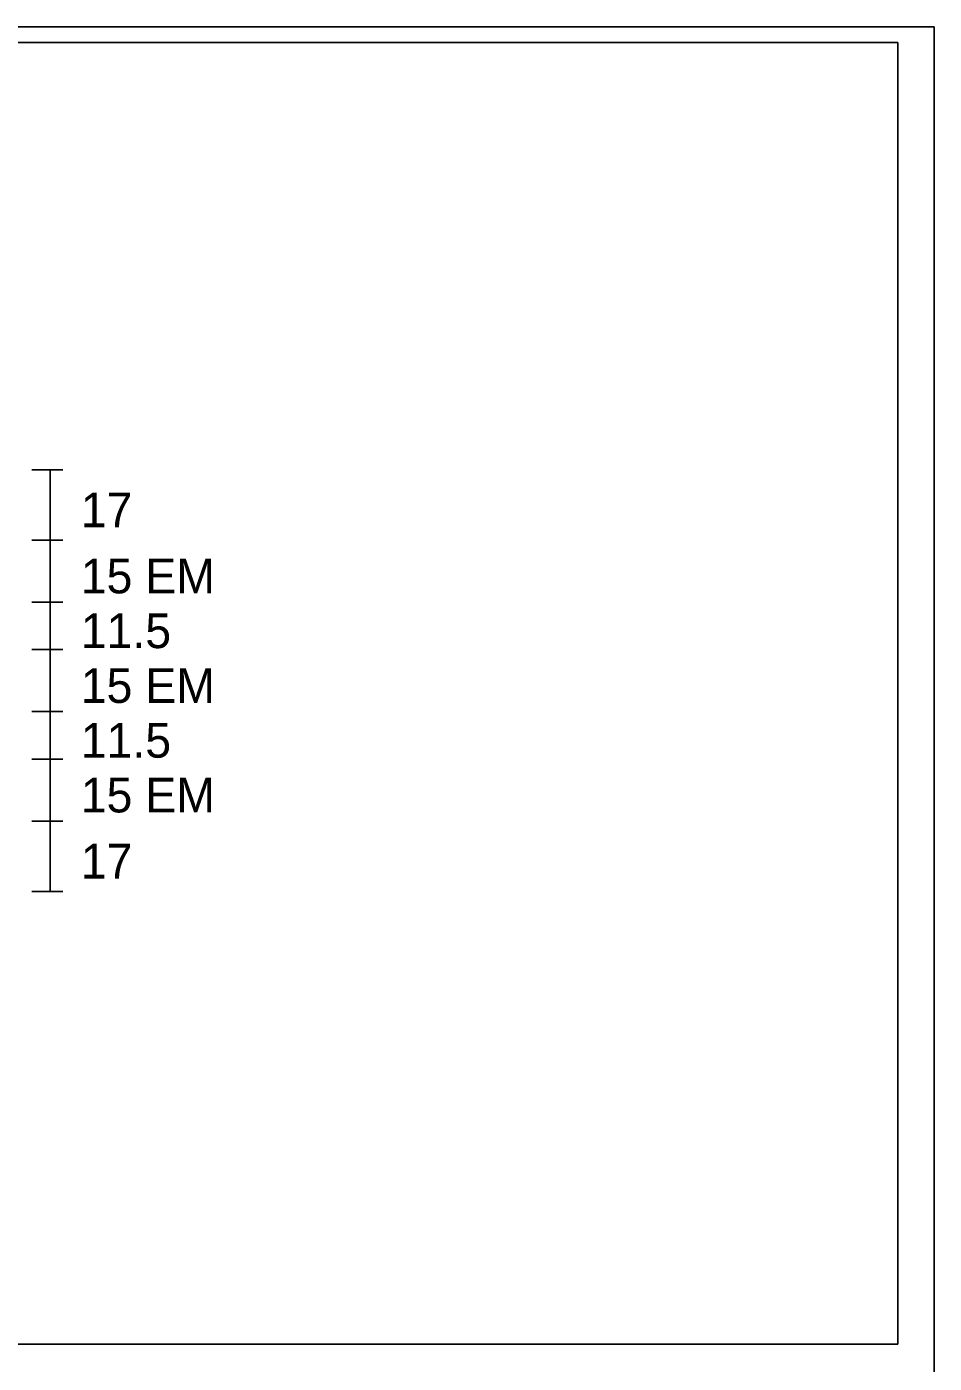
# Model space of a CAD drawing. Extents: x 10268147 to 10268469, y 2141099 to 2141204.
# Drawn here: x 10268288.02 to 10268306.32, y 2141177.01 to 2141203.96 of the extents above; entities that cross this region are included whole.
import ezdxf

# ---------------------------------------------------------------- set-up
doc = ezdxf.new("R2010")
doc.units = 0
for name, color, linetype in [('61', 7, 'Continuous'), ('GSDims', 7, 'Continuous'), ('SheetLinesMisc2_dp', 7, 'Continuous')]:
    doc.layers.add(name, color=color, linetype=linetype)

msp = doc.modelspace()

# ---------------------------------------------------------------- linework, layer by layer
at = {"layer": '61'}
for p, q in [((10268230.252, 2141203.638), (10268305.587, 2141203.638)), ((10268305.587, 2141177.389), (10268305.587, 2141203.638)), ((10268230.252, 2141177.389), (10268305.587, 2141177.389))]:
    msp.add_line(p, q, dxfattribs=at)
at = {"layer": 'GSDims'}
for p, q in [((10268288.122, 2141195.021), (10268288.747, 2141195.021)), ((10268288.497, 2141193.605), (10268288.497, 2141195.021)), ((10268288.122, 2141193.605), (10268288.747, 2141193.605)), ((10268288.122, 2141193.605), (10268288.747, 2141193.605)), ((10268288.497, 2141193.605), (10268288.497, 2141192.355)), ((10268288.122, 2141192.355), (10268288.747, 2141192.355)), ((10268288.122, 2141192.355), (10268288.747, 2141192.355)), ((10268288.497, 2141191.396), (10268288.497, 2141192.355)), ((10268288.122, 2141191.396), (10268288.747, 2141191.396)), ((10268288.122, 2141191.396), (10268288.747, 2141191.396)), ((10268288.497, 2141191.396), (10268288.497, 2141190.146)), ((10268288.122, 2141190.146), (10268288.747, 2141190.146)), ((10268288.122, 2141190.146), (10268288.747, 2141190.146)), ((10268288.497, 2141189.188), (10268288.497, 2141190.146)), ((10268288.122, 2141189.188), (10268288.747, 2141189.188)), ((10268288.122, 2141189.188), (10268288.747, 2141189.188)), ((10268288.497, 2141189.188), (10268288.497, 2141187.938)), ((10268288.122, 2141187.938), (10268288.747, 2141187.938)), ((10268288.122, 2141187.938), (10268288.747, 2141187.938)), ((10268288.497, 2141186.521), (10268288.497, 2141187.938)), ((10268288.122, 2141186.521), (10268288.747, 2141186.521))]:
    msp.add_line(p, q, dxfattribs=at)
at = {"layer": 'SheetLinesMisc2_dp'}
for p, q in [((10268153.14, 2141203.955), (10268306.32, 2141203.955)), ((10268306.32, 2141108.602), (10268306.32, 2141203.954))]:
    msp.add_line(p, q, dxfattribs=at)

# ---------------------------------------------------------------- texts
at = {"layer": 'GSDims'}
for s, p in [('17', (10268289.111, 2141193.863)), ('15 EM', (10268289.111, 2141192.53)), ('11.5', (10268289.111, 2141191.426)), ('15 EM', (10268289.111, 2141190.321)), ('11.5', (10268289.111, 2141189.217)), ('15 EM', (10268289.111, 2141188.113)), ('17', (10268289.111, 2141186.78))]:
    msp.add_text(s, height=0.7, dxfattribs=at).set_placement(p)

doc.saveas('drawing.dxf')
